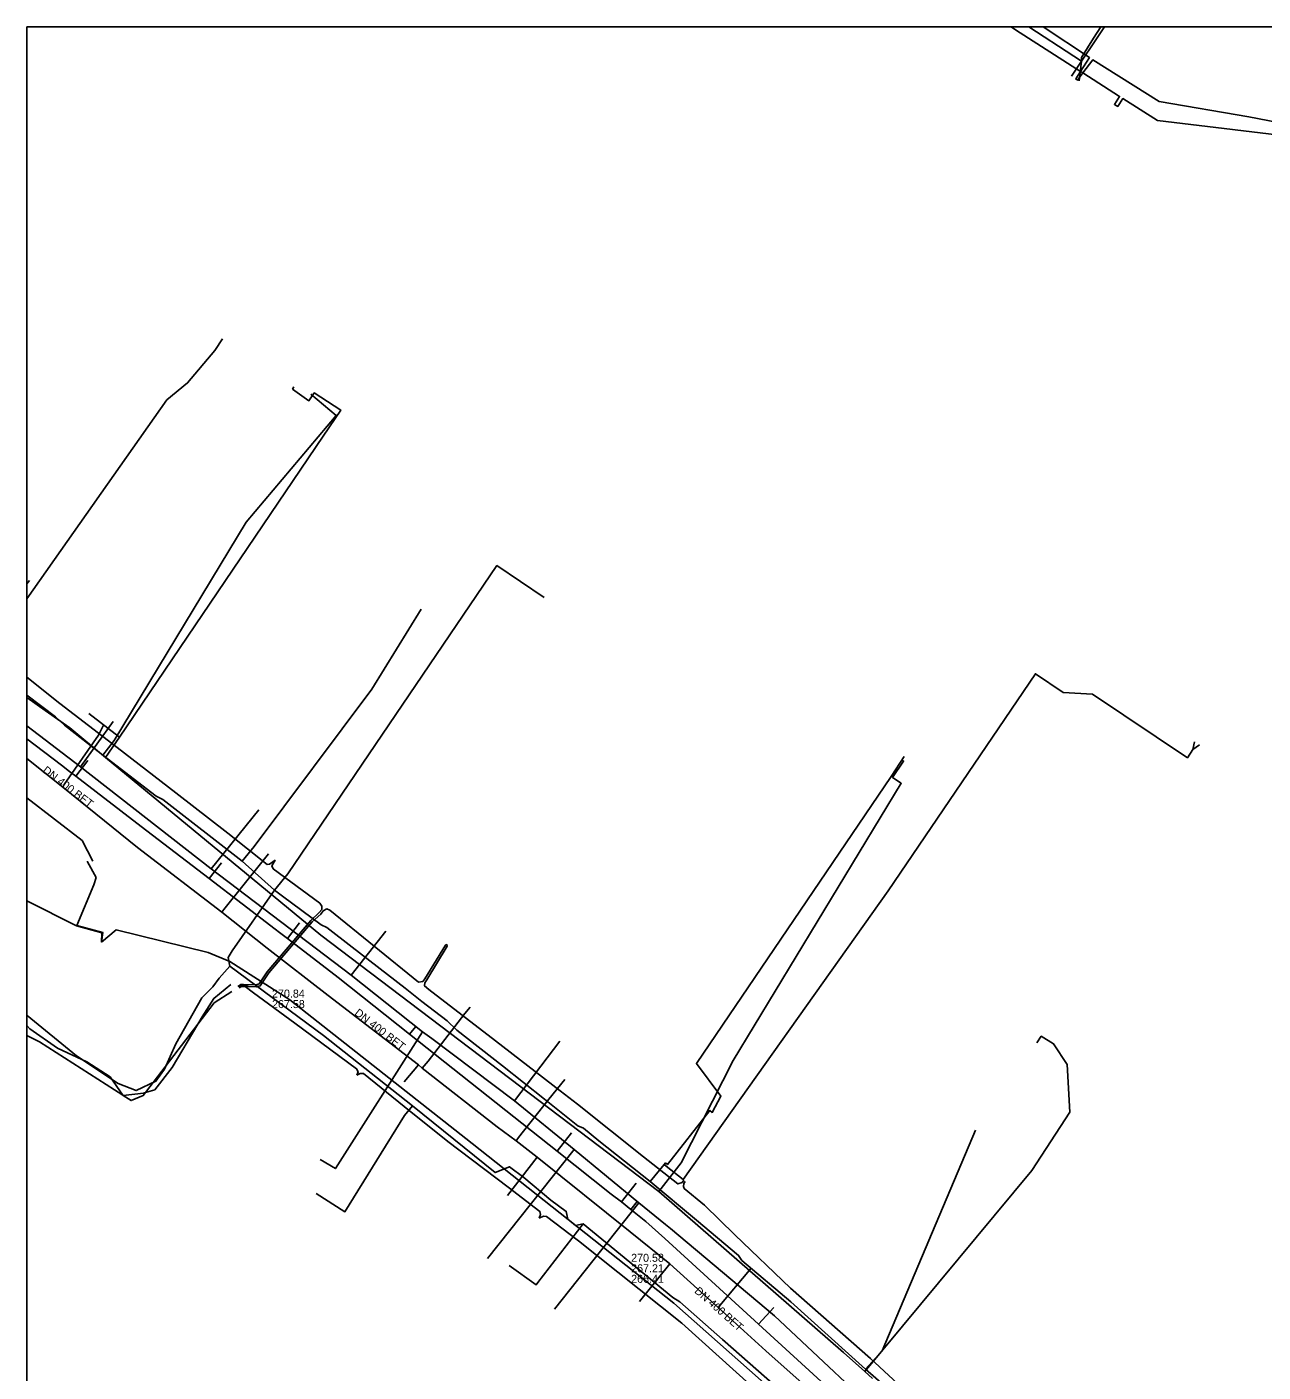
# Model space of a CAD drawing. Extents: x -600309 to -598967, y -1161267 to -1160292.
# Drawn here: x -600308.5 to -600185, y -1160426.8 to -1160292.3 of the extents above; entities that cross this region are included whole.
import ezdxf

# ---------------------------------------------------------------- set-up
doc = ezdxf.new("R2010")
doc.units = 0
for name, color, linetype in [('Vrstva 12', 7, 'Continuous'), ('Vrstva 13', 7, 'Continuous'), ('Vrstva 19', 7, 'Continuous'), ('Vrstva 42', 7, 'Continuous'), ('Vrstva 55', 7, 'Continuous'), ('Vrstva 63', 7, 'Continuous'), ('Vrstva 9', 7, 'Continuous')]:
    doc.layers.add(name, color=color, linetype=linetype)

msp = doc.modelspace()

# ---------------------------------------------------------------- linework, layer by layer
at = {"layer": 'Vrstva 12'}
for p, q in [((-600208.42, -1160292.35), (-600203.93, -1160295.28)), ((-600308.54, -1160359.37), (-600306.73, -1160360.66))]:
    msp.add_line(p, q, dxfattribs=at)
for points in [[(-600203.19, -1160295.76), (-600203.17, -1160295.4), (-600201.99, -1160293.48), (-600201.24, -1160292.35)], [(-600203.93, -1160295.28), (-600203.19, -1160295.76)], [(-600203.19, -1160295.76), (-600203.42, -1160297.75)], [(-600308.54, -1160349.51), (-600294.56, -1160329.63), (-600292.48, -1160327.93), (-600289.78, -1160324.7), (-600289, -1160323.54)], [(-600300.94, -1160365.14), (-600299.81, -1160363.68), (-600286.63, -1160341.86), (-600277.63, -1160331.2), (-600280.17, -1160329.07)], [(-600283.79, -1160378.62), (-600282.47, -1160377), (-600261.58, -1160346.19), (-600256.85, -1160349.39)], [(-600287.04, -1160375.74), (-600285.82, -1160374.28), (-600274.08, -1160358.54), (-600269.14, -1160350.56)], [(-600244.88, -1160406.05), (-600244.66, -1160406.23), (-600242.97, -1160407.55), (-600222.49, -1160378.71), (-600207.77, -1160357.01), (-600205, -1160358.89), (-600202.09, -1160359.04), (-600192.59, -1160365.4), (-600192.04, -1160364.57)], [(-600300.94, -1160365.14), (-600304.77, -1160362.13), (-600305.67, -1160361.32), (-600308.54, -1160359.13)], [(-600306.73, -1160360.66), (-600304.26, -1160362.42)], [(-600299.3, -1160363.33), (-600302.35, -1160360.99)], [(-600304.26, -1160362.42), (-600300.69, -1160365.37)], [(-600300.69, -1160365.37), (-600299.3, -1160363.33)], [(-600192.04, -1160364.57), (-600191.9, -1160363.8)], [(-600287.04, -1160375.74), (-600294.97, -1160369.57), (-600295.62, -1160369.25), (-600300.94, -1160365.14)], [(-600192.04, -1160364.57), (-600191.38, -1160364.11)], [(-600245.39, -1160408.76), (-600279.18, -1160383.14), (-600300.69, -1160365.37)], [(-600245.39, -1160408.76), (-600243.17, -1160405.9), (-600237.98, -1160395.67), (-600221.19, -1160367.95), (-600222.05, -1160367.37), (-600220.95, -1160365.74), (-600221.12, -1160365.63)], [(-600244.75, -1160405.9), (-600244.54, -1160406.07), (-600240.31, -1160400.66), (-600240.07, -1160400.85), (-600239.2, -1160399.24), (-600241.65, -1160395.95), (-600222.18, -1160367.28), (-600220.89, -1160365.29)], [(-600283.79, -1160378.62), (-600287.04, -1160375.74)], [(-600283.79, -1160378.62), (-600288.05, -1160384.7), (-600288.43, -1160385.36), (-600288.27, -1160386.23)], [(-600282.99, -1160379.23), (-600283.79, -1160378.62)], [(-600246.27, -1160407.76), (-600251.39, -1160403.68), (-600252.93, -1160402.42), (-600253.5, -1160402.18), (-600256.84, -1160399.51), (-600261.01, -1160396.2), (-600265.59, -1160392.63), (-600266.56, -1160391.68), (-600269.08, -1160389.75), (-600270.76, -1160388.44), (-600276.06, -1160384.34), (-600278.58, -1160382.35), (-600279.15, -1160382.11), (-600282.99, -1160379.23)], [(-600288.27, -1160386.23), (-600289.34, -1160387.43)], [(-600288.27, -1160386.23), (-600278.9, -1160393.16), (-600270.01, -1160400.2)], [(-600289.34, -1160387.43), (-600289.97, -1160388.3), (-600291.08, -1160389.39), (-600293.67, -1160394), (-600294.8, -1160396.53), (-600295.66, -1160397.74), (-600297.61, -1160398.66), (-600299.44, -1160397.95), (-600303.59, -1160395.2), (-600308.51, -1160391.17), (-600308.54, -1160391.14)], [(-600270.01, -1160400.2), (-600270.81, -1160401.15), (-600276.76, -1160410.77), (-600279.63, -1160408.94)], [(-600270.01, -1160400.2), (-600261.75, -1160406.87), (-600260.34, -1160406.28), (-600258.89, -1160407.37), (-600256.18, -1160409.61), (-600254.66, -1160410.75), (-600254.5, -1160411.52), (-600253.74, -1160412.16), (-600252.98, -1160411.99)], [(-600223.09, -1160424.68), (-600213.76, -1160402.62)], [(-600246.27, -1160407.76), (-600244.88, -1160406.05)], [(-600244.88, -1160406.05), (-600244.75, -1160405.9)], [(-600224.77, -1160426.52), (-600232.22, -1160419.79), (-600237.1, -1160415.65), (-600237.44, -1160415.15), (-600241.64, -1160411.63), (-600246.27, -1160407.76)], [(-600245.39, -1160408.76), (-600226.96, -1160424.83), (-600224.81, -1160426.76)], [(-600252.98, -1160411.99), (-600257.48, -1160417.84)], [(-600252.98, -1160411.99), (-600244.01, -1160419.35), (-600243.31, -1160419.79), (-600239.05, -1160423.54), (-600232.95, -1160428.92), (-600228.9, -1160432.57), (-600224.54, -1160436.58), (-600223.6, -1160437.32), (-600220.27, -1160440.45), (-600211.09, -1160449.13), (-600205.57, -1160454.51), (-600198.75, -1160461.15), (-600191.51, -1160468.01), (-600187.68, -1160471.64), (-600185.4, -1160474.12)], [(-600257.48, -1160417.84), (-600257.65, -1160418.07), (-600260.37, -1160416.14)], [(-600224.77, -1160426.52), (-600223.09, -1160424.68)], [(-600224.81, -1160426.76), (-600224.06, -1160427.43)], [(-600211.9, -1160438.32), (-600216.56, -1160433.97), (-600219.59, -1160431), (-600224.77, -1160426.52)]]:
    msp.add_lwpolyline(points, dxfattribs=at)
at = {"layer": 'Vrstva 13'}
for p, q in [((-600204.16, -1160297.26), (-600200.87, -1160292.35)), ((-600308.54, -1160348.03), (-600308.29, -1160347.69)), ((-600303.18, -1160366.31), (-600299.92, -1160361.79)), ((-600290.12, -1160376.49), (-600285.38, -1160370.6)), ((-600276.13, -1160387.14), (-600272.69, -1160382.74)), ((-600259.81, -1160399.69), (-600255.28, -1160393.73)), ((-600253.85, -1160404.55), (-600262.51, -1160415.44)), ((-600247.41, -1160409.89), (-600255.83, -1160420.53))]:
    msp.add_line(p, q, dxfattribs=at)
for points in [[(-600299.3, -1160363.33), (-600278.93, -1160333.26), (-600277.19, -1160330.65), (-600279.83, -1160328.94), (-600280.37, -1160329.71), (-600282.02, -1160328.56)], [(-600282.02, -1160328.56), (-600281.86, -1160328.33)], [(-600221.37, -1160432.92), (-600233.85, -1160421.19), (-600244.24, -1160412.45), (-600244.73, -1160412.04), (-600247.41, -1160409.89), (-600253.85, -1160404.55), (-600259.81, -1160399.69), (-600268.1, -1160393.45), (-600269.01, -1160392.78), (-600276.13, -1160387.14), (-600290.12, -1160376.49), (-600303.18, -1160366.31), (-600308.54, -1160362.2)], [(-600269.01, -1160392.78), (-600277.71, -1160406.47), (-600279.25, -1160405.55)], [(-600207.64, -1160393.88), (-600207.2, -1160393.23), (-600205.96, -1160393.98), (-600204.62, -1160396.05), (-600204.34, -1160400.83), (-600208.13, -1160406.65), (-600224.81, -1160426.76)]]:
    msp.add_lwpolyline(points, dxfattribs=at)
at = {"layer": 'Vrstva 19'}
for points in [[(-600304.95, -1160368.33), (-600304.81, -1160368.08), (-600301.39, -1160363.14), (-600300.85, -1160362.06)], [(-600308.54, -1160365.49), (-600304.95, -1160368.33), (-600297.49, -1160374.38), (-600289.07, -1160380.84), (-600284.53, -1160384.43), (-600278.44, -1160389.15), (-600269.43, -1160396.1), (-600269.05, -1160396.42), (-600261.54, -1160402.29), (-600259.67, -1160403.7), (-600257.56, -1160405.31), (-600248.28, -1160412.77), (-600244.32, -1160415.97), (-600239.47, -1160420.35), (-600234.72, -1160424.68), (-600230.5, -1160428.45)], [(-600289.07, -1160380.84), (-600288.86, -1160380.56), (-600285.08, -1160375.82), (-600284.39, -1160375.01)], [(-600269.05, -1160396.42), (-600268.44, -1160395.72), (-600264.79, -1160390.97), (-600264.25, -1160390.34)], [(-600269.43, -1160396.1), (-600270.86, -1160397.78)], [(-600254.8, -1160397.56), (-600256.38, -1160399.54), (-600259.41, -1160403.35)], [(-600259.67, -1160403.7), (-600259.41, -1160403.35)], [(-600257.56, -1160405.31), (-600260.53, -1160409.16)], [(-600244.32, -1160415.97), (-600247.35, -1160419.75)], [(-600239.47, -1160420.35), (-600236.19, -1160416.42)]]:
    msp.add_lwpolyline(points, dxfattribs=at)
at = {"layer": 'Vrstva 42'}
for points in [[(-600210.21, -1160292.35), (-600209.76, -1160292.64), (-600203.27, -1160296.8), (-600203.03, -1160296.95), (-600199.37, -1160299.3), (-600199.89, -1160300.09), (-600199.72, -1160300.19), (-600199.55, -1160300.3), (-600199.03, -1160299.51), (-600195.59, -1160301.71), (-600180.32, -1160303.52), (-600178.53, -1160304.69), (-600179.24, -1160305.77), (-600179.07, -1160305.88), (-600178.9, -1160305.99), (-600178.2, -1160304.9), (-600174.59, -1160307.25), (-600172.58, -1160308.55), (-600172.3, -1160308.72), (-600162.14, -1160315.29), (-600159.79, -1160316.78), (-600159.72, -1160316.82), (-600160.24, -1160317.61), (-600160.45, -1160317.93)], [(-600207, -1160292.35), (-600202.38, -1160295.42), (-600203.27, -1160296.8), (-600203.75, -1160297.54), (-600203.57, -1160297.66), (-600203.03, -1160296.95), (-600202.05, -1160295.64), (-600195.43, -1160299.81), (-600186.45, -1160301.34), (-600179.4, -1160302.7), (-600175.42, -1160305.04), (-600175.11, -1160303.62), (-600174.99, -1160295.49), (-600174.73, -1160293.3), (-600174.13, -1160292.35)], [(-600308.54, -1160357.33), (-600305.25, -1160359.99), (-600299.54, -1160364.38), (-600293.66, -1160368.89), (-600288.45, -1160372.93), (-600284.55, -1160376.06), (-600284.32, -1160376.02), (-600283.74, -1160375.65), (-600284.07, -1160376.21), (-600283.95, -1160376.49), (-600279.28, -1160379.94), (-600279.08, -1160380.22), (-600279.09, -1160380.57), (-600279.33, -1160380.88), (-600280.18, -1160381.66), (-600284.52, -1160386.79), (-600285.34, -1160388.01), (-600285.62, -1160388.09), (-600286.9, -1160388.05), (-600287.17, -1160388.07), (-600287.47, -1160388.26)], [(-600242.92, -1160407.63), (-600243.08, -1160407.84), (-600243.5, -1160407.99), (-600246.94, -1160405.3), (-600253.53, -1160400.02), (-600255.26, -1160398.69), (-600261.72, -1160393.68), (-600268.39, -1160388.57), (-600268.81, -1160388.21), (-600268.77, -1160387.88), (-600268.59, -1160387.59), (-600266.54, -1160384.23), (-600266.57, -1160384.08), (-600266.72, -1160384.14), (-600268.77, -1160387.49), (-600269, -1160387.75), (-600269.43, -1160387.84), (-600278.29, -1160380.64), (-600278.56, -1160380.5), (-600278.93, -1160380.69), (-600279.19, -1160381.02), (-600280.04, -1160381.8), (-600284.36, -1160386.91), (-600285.22, -1160388.19), (-600285.6, -1160388.29), (-600286.45, -1160388.26), (-600286.71, -1160388.16), (-600286.9, -1160388.15), (-600287.14, -1160388.17), (-600287.37, -1160388.32)], [(-600288.17, -1160388.06), (-600289.85, -1160389.45), (-600291.03, -1160391.3), (-600291.46, -1160392.02), (-600294.03, -1160396.36), (-600295.77, -1160398.58), (-600296.68, -1160398.85), (-600296.88, -1160398.91), (-600298.94, -1160399.15), (-600298.95, -1160399.15), (-600298.96, -1160399.14), (-600300.22, -1160397.3), (-600302.55, -1160395.78), (-600305.47, -1160394.42), (-600308.26, -1160392.5), (-600308.54, -1160392.17)], [(-600288.06, -1160388.75), (-600289.82, -1160389.88), (-600291.46, -1160392.02), (-600296.68, -1160398.85), (-600296.92, -1160399.16), (-600298.13, -1160399.67), (-600298.94, -1160399.15), (-600298.96, -1160399.14), (-600307.28, -1160393.78), (-600308.54, -1160393.16)], [(-600275.57, -1160397.12), (-600275.57, -1160397.12), (-600275.45, -1160396.78), (-600275.6, -1160396.49), (-600281.77, -1160391.93), (-600285.91, -1160388.89), (-600286.75, -1160388.26), (-600286.9, -1160388.25), (-600287.11, -1160388.27), (-600287.32, -1160388.4)], [(-600275.57, -1160397.12), (-600275.57, -1160397.12), (-600275.24, -1160396.95), (-600274.91, -1160396.95), (-600270.85, -1160400.25), (-600266.48, -1160403.75), (-600260.46, -1160408.33), (-600257.28, -1160410.74), (-600257.22, -1160411.05), (-600257.35, -1160411.41)], [(-600208.02, -1160441.02), (-600212.22, -1160436.77), (-600217.91, -1160431.35), (-600224.27, -1160425.45), (-600232.25, -1160418.43), (-600237.81, -1160413.09), (-600240.84, -1160410.12), (-600242.87, -1160408.45), (-600242.95, -1160408.24), (-600242.89, -1160407.95), (-600242.76, -1160407.76)], [(-600257.35, -1160411.41), (-600256.93, -1160411.23), (-600256.62, -1160411.25), (-600253.43, -1160413.69), (-600249.49, -1160416.81), (-600243.11, -1160421.93), (-600235.99, -1160428.33), (-600229.05, -1160434.52), (-600222.94, -1160440.27), (-600217.71, -1160445.27), (-600213.52, -1160449.19), (-600213.4, -1160449.59), (-600213.47, -1160450.15), (-600213.67, -1160450.44)]]:
    msp.add_lwpolyline(points, dxfattribs=at)
at = {"layer": 'Vrstva 55'}
for points in [[(-600308.54, -1160369.39), (-600303.01, -1160373.68), (-600301.94, -1160375.74)], [(-600302.54, -1160375.83), (-600302.48, -1160375.79), (-600301.63, -1160377.36), (-600301.84, -1160378.11), (-600303.57, -1160382.17), (-600300.94, -1160382.87), (-600301.1, -1160383.83)], [(-600301.1, -1160383.83), (-600301.07, -1160382.9), (-600303.6, -1160382.21), (-600308.54, -1160379.71)], [(-600301.1, -1160383.83), (-600299.63, -1160382.61), (-600290.42, -1160384.87), (-600288.27, -1160385.78), (-600282.28, -1160389.58), (-600264.06, -1160403.94), (-600243.9, -1160419.91), (-600224.43, -1160437.18), (-600209.21, -1160451.33), (-600188.22, -1160471.86)]]:
    msp.add_lwpolyline(points, dxfattribs=at)
at = {"layer": 'Vrstva 63'}
msp.add_lwpolyline([(-600308.54, -1160292.35), (-598967.11, -1160292.35), (-598967.11, -1161267.03), (-600308.54, -1161267.03)], close=True, dxfattribs=at)
at = {"layer": 'Vrstva 9'}
for p, q in [((-600302.44, -1160365.67), (-600303.66, -1160367.25)), ((-600289.11, -1160375.89), (-600290.33, -1160377.48)), ((-600281.29, -1160381.9), (-600282.5, -1160383.48)), ((-600269.68, -1160392.25), (-600270.3, -1160393.03)), ((-600254.14, -1160402.9), (-600255.55, -1160404.72)), ((-600247.68, -1160407.91), (-600249.14, -1160409.8)), ((-600247.58, -1160409.76), (-600248.2, -1160410.55)), ((-600233.9, -1160420.35), (-600235.45, -1160422.02))]:
    msp.add_line(p, q, dxfattribs=at)
for points in [[(-600308.54, -1160363.5), (-600305.1, -1160366.14), (-600304.28, -1160366.78), (-600303.66, -1160367.25), (-600297.11, -1160372.28), (-600290.33, -1160377.48), (-600283.73, -1160382.54), (-600283.31, -1160382.87), (-600282.5, -1160383.48), (-600277.44, -1160387.37)], [(-600277.44, -1160387.37), (-600270.3, -1160393.03), (-600255.55, -1160404.72), (-600250.15, -1160409.01), (-600249.14, -1160409.8), (-600248.2, -1160410.55), (-600246.7, -1160411.74)], [(-600246.7, -1160411.74), (-600244.82, -1160413.46), (-600235.45, -1160422.02), (-600217.49, -1160438.44), (-600215.77, -1160440), (-600215.11, -1160440.61)]]:
    msp.add_lwpolyline(points, dxfattribs=at)

# ---------------------------------------------------------------- texts
at = {"layer": 'Vrstva 12'}
for rotation, p in [(322.5179, (-600307.05, -1160366.8)), (322.2315, (-600275.87, -1160391.04)), (318.6126, (-600241.91, -1160418.8))]:
    msp.add_text('DN 400 BET', height=0.8, rotation=rotation, dxfattribs=at).set_placement(p)
for s, p in [('270.84', (-600284.05, -1160389.37)), ('267.58', (-600284.05, -1160390.42)), ('270.58', (-600248.17, -1160415.78)), ('267.21', (-600248.17, -1160416.83)), ('266.41', (-600248.17, -1160417.88))]:
    msp.add_text(s, height=0.8, dxfattribs=at).set_placement(p)

doc.saveas('drawing.dxf')
